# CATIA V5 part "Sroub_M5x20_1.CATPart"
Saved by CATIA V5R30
Part number: Sroub_M5x20_1
Nomenclature: E1200/5x20
Description: MEUSBURGER
Publications: "DrillHole", "TapHole", "Base"
Bounding box of the stored display mesh (mm): x -4.249 to 4.249, y -4.245 to 4.245, z -5 to 20
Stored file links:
  E:\Bakalarka\Model\Forma_v7\Sroub_M5x20_1.CATPart
  E:\dev\MoldDesign\intel_a\startup\components\MoldCatalog\CapScrew\Meusburger\CapScrew_E1200\TableE1200.txt
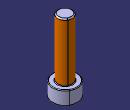
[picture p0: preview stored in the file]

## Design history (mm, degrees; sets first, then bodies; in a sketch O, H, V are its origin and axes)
Parameters
  Ref = "E1200/5x20" {design table}
  L = 20 mm {design table}
  D = 5 mm {design table}
  D1 = 5 mm {design table}
  D3 = 8.5 mm {design table}
  L1 = 20 mm {design table}
  L2 = 20 mm {design table}
  L3 = 5 mm {design table}
  SW = 4 mm {design table}
  dkren = 4.02 mm {design table}
  L4 = 2.5 mm {design table}
  R = 0.2 mm {design table}
  R1 = 0.5 mm {design table}
  F = 0.4 mm {design table}
  kdkern = 4.13 mm {design table}
  kd1 = 5.5 mm {design table}
  kl1 = 15 mm {design table}
  kd3 = 9.5 mm {design table}
  kl3 = 6 mm {design table}
  kl = 30 mm {design table}
  c = 4 mm {design table}
  ThreadString = "M5" {design table}
  Mat = "" {design table}
  HeatTreat = "" {design table}
  SupplierRef = "Meusburger 2017"
  BmpRef = "F_MldCapScrewLD"
  DrillHole_Length = 225 mm
  HeadThick = 5 mm {= L3}
  HeadDiam = 8.5 mm {= D3}
  ScrewThread = 20 mm {= Thread1.Depth}
  ScrewPitch = 0.8 mm {= Thread1.Pitch}
Set1 "BaseBody"
  Point1 "Base": (0, 0, 0)
  Plane1: type Offset, RefPlane xy-plane, Offset 225 {= DrillHole_Length}, reversed
Body1 "PartBody" (main body)
  Sketch1 on yz-plane, origin (0, 0, 0), H (0, 0, -1), V (0, 1, 0)
    point P1 (5, 0)
    line L1 (5, 0) -> (5, -4.25)
    line L2 (5, -4.25) -> (0, -4.25)
    line L3 (0, -4.25) -> (0, -2.5)
    point P5 (0, -2.5)
    line L4 (0, -2.5) -> (-20, -2.5)
    line L5 (-20, -2.5) -> (-20, 0)
    point P7 (-20, 0)
    axis line L6 (-20, 0) -> (5, 0)
    point P8 (5, 0)
    construction line L7 (0, -2.5) -> (0, -2.5)
    line L8 (0, 0) -> (-20, 0)
    point P9 (-20, -2.5)
    point P10 (-20, -2.5)
    line L9 (0, 0) -> (5, 0)
    length L1 = 4.25 {= D3 /2}
    distance L1 L3 = 5 {= L3}
    distance L4 L6 = 2.5 {= D /2}
    distance L3 L5 = 20 {= L}
    distance L5 P5 = 20 {= L1}
    coincidence: P1 L6, L6 H, P8 L1, P9 P10, P7 L5, L3 V
    vertical: L1 V, L3 V, L5 V
    horizontal: L2 H, L4 H, L7 H, L8 H, L9 H
  Shaft1: profile Sketch1, axis Sketch1.L6, angle 360
  Sketch2 on face of Shaft1 from Sketch1.L1, origin (0, 0, -5), H (1, 0, 0), V (0, -1, 0)
    point P1 (-1.1547, -2)
    point P2 (1.1547, -2)
    point P3 (2.3094, 0)
    point P4 (1.1547, 2)
    point P5 (-1.1547, 2)
    point P6 (-2.3094, 0)
    point P7 (0, -2)
    line L1 (-1.1547, -2) -> (1.1547, -2)
    line L2 (1.1547, -2) -> (2.3094, 0)
    line L3 (2.3094, 0) -> (1.1547, 2)
    line L4 (1.1547, 2) -> (-1.1547, 2)
    line L5 (-1.1547, 2) -> (-2.3094, 0)
    line L6 (-2.3094, 0) -> (-1.1547, -2)
    construction line L7 (0, 0) -> (0, -2)
    construction circle A1 centre (0, 0) radius 2.3094
    construction arc A2 centre (-1.1547, 2) radius 2.3094 from (1.1547, 2) to (-2.3094, 0) cw
    construction arc A3 centre (1.1547, -2) radius 2.3094 from (2.3094, 0) to (-1.1547, -2) ccw
    point P8 (-1.1547, 2)
    point P9 (1.1547, -2)
    distance L1 L4 = 4 {= SW}
    coincidence: A1 P1, A1 P2, A1 P3, A1 P4, A1 P5, A1 P6, A2 P4, A2 P6, A2 O, P8 P5, A3 P3, A3 P1, A3 O, P9 P2, P3 H
    midpoint: P7 L1
  Pocket1: profile Sketch2, direction (0, 0, 1), length 2.5 {= L4}
  Thread1: "M5", diameter 5, depth 20 {= L2}, pitch 0.8, on face of Shaft1 from Sketch1.L4, from face of Shaft1 from Sketch1.L5
  Fillet1: radius 0.5 {= R1}, on edge [face of Shaft1 from Sketch1.L2 | face of Shaft1 from Sketch1.L1]
  Fillet2: radius 0.2 {= R}, on edge [face of Shaft1 from Sketch1.L3 | face of Shaft1 from Sketch1.L2]
  Fillet3: radius 0.2 {= R}, on edge [face of Shaft1 from Sketch1.L4 | face of Shaft1 from Sketch1.L3]
  Chamfer1: length 0.4 {= F}, angle 45, on edge [face of Shaft1 from Sketch1.L5 | face of Shaft1 from Sketch1.L4]
Body2 "DrillHole"
  Sketch3 on Plane1, origin (22.3066, -22.3066, -225), H (1, 0, 0), V (0, 1, 0)
    point P1 (-22.3066, 22.3066)
    reference projected circle E1 centre (-22.3066, 22.3066) radius 4.25 from edge [face of Shaft1 from Sketch1.L3 | face of Shaft1 from Sketch1.L2]
    concentricity: E1 P1
  Hole1: placed by Sketch3, at (0, 0, -225) direction (0, 0, 1), diameter 5.5 {= kd1}, depth 245 {= DrillHole_Length +L1}, counterbore diameter 9.5 {= kd3}, counterbore depth 225 {= DrillHole_Length}
Body3 "TapHole"
  Sketch4 on Plane1, origin (0, 0, -225), H (1, 0, 0), V (0, 1, 0)
    point P1 (0, 0)
    reference projected point E1 (0, 0) from Point1
    coincidence: E1 P1
  Hole2: placed by Sketch4, at (0, 0, -225) direction (0, 0, 1), diameter 4.134, depth 255 {= DrillHole_Length +kl}, V-bottom angle 120, threaded "M5", thread diameter 5, thread depth 255 {= DrillHole_Length +kl}, pitch 0.8
Relations
  design table "TableE1200", configuration 35, drives Ref, L, D, D1, D3, L1, L2, L3, SW, dkren, L4, R, R1, F, kdkern, kd1, kl1, kd3, kl3, kl, c, ThreadString, Mat, HeatTreat
  Thread1.ThreadDescription = ThreadString
  Hole2.ThreadDescription = ThreadString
